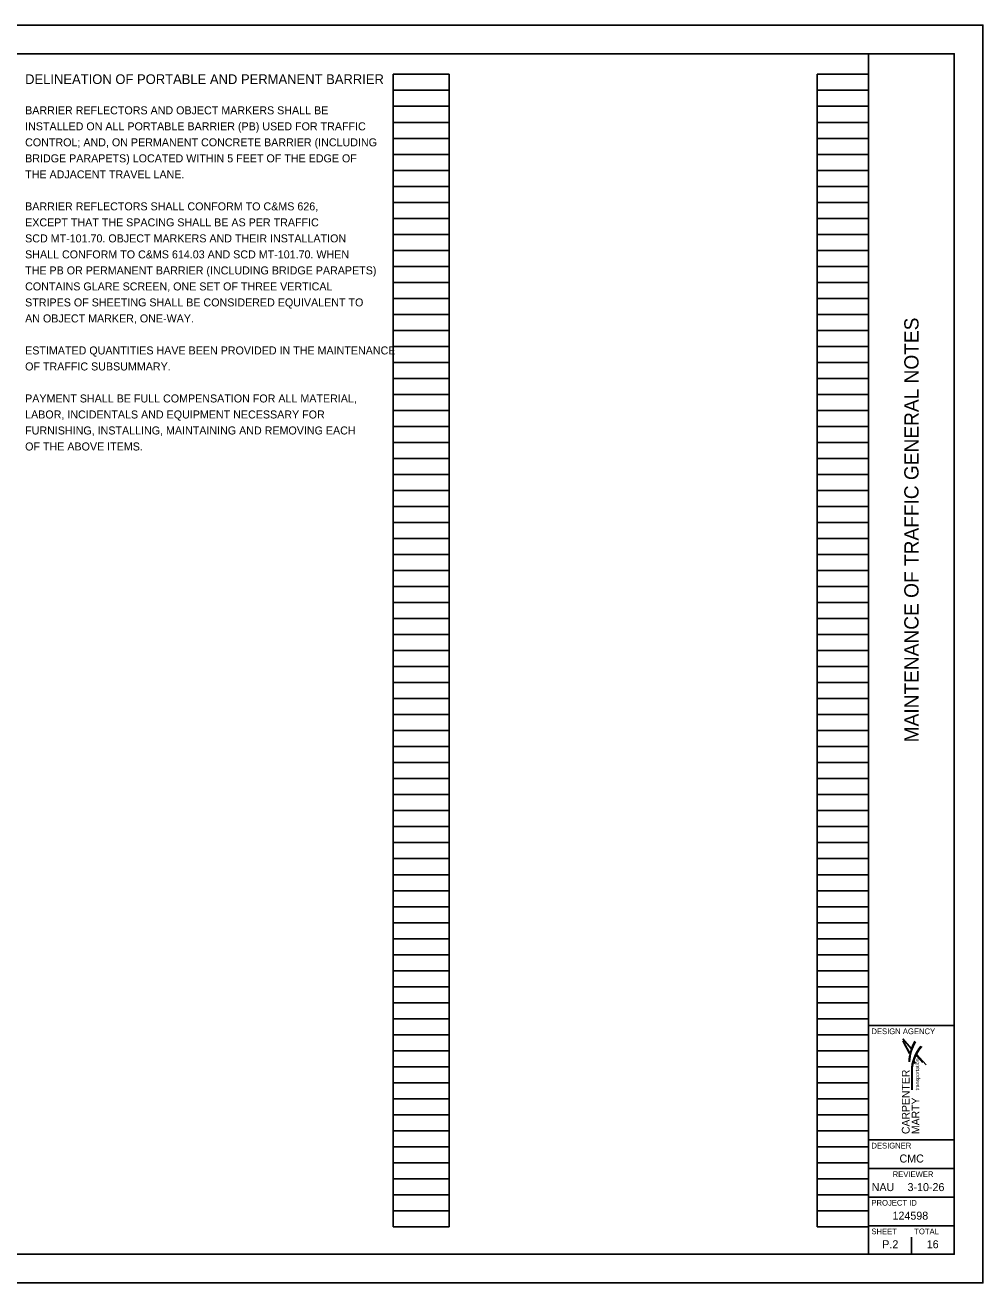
# Model space of a CAD drawing. Extents: x 0 to 34, y 0 to 22.
# Drawn here: x 17.24 to 34, y 0 to 22 of the extents above; entities that cross this region are included whole.
import ezdxf

# ---------------------------------------------------------------- set-up
doc = ezdxf.new("R2010")
doc.units = 0
for name, color, linetype in [('SH_Border', 7, 'Continuous'), ('SH_Cut_Line', 7, 'Continuous'), ('SH_Data', 7, 'Continuous'), ('SH_Text', 7, 'Continuous')]:
    doc.layers.add(name, color=color, linetype=linetype)

msp = doc.modelspace()

# ---------------------------------------------------------------- linework, layer by layer
at = {"layer": 'SH_Border'}
for p, q in [((32, 0.5), (32, 21.5)), ((32, 4.5), (33.5, 4.5)), ((32, 2.5), (33.5, 2.5)), ((32, 2), (33.5, 2)), ((32, 1.5), (33.5, 1.5)), ((32, 1), (33.5, 1))]:
    msp.add_line(p, q, dxfattribs=at)
msp.add_lwpolyline([(1.5, 21.5), (33.5, 21.5), (33.5, 0.5), (1.5, 0.5)], close=True, dxfattribs=at)
at = {"layer": 'SH_Cut_Line'}
msp.add_lwpolyline([(0, 0), (34, 0), (34, 22), (0, 22)], close=True, dxfattribs=at)
at = {"layer": 'SH_Data'}
for p, q in [((23.68, 0.98), (23.68, 21.14)), ((23.68, 21.14), (24.66, 21.14)), ((24.66, 0.98), (24.66, 21.14)), ((31.1, 0.98), (31.1, 21.14)), ((31.1, 21.14), (32, 21.14)), ((32, 0.98), (32, 21.14)), ((23.68, 20.86), (24.66, 20.86)), ((31.1, 20.86), (32, 20.86)), ((23.68, 20.58), (24.66, 20.58)), ((31.1, 20.58), (32, 20.58)), ((23.68, 20.3), (24.66, 20.3)), ((31.1, 20.3), (32, 20.3)), ((23.68, 20.02), (24.66, 20.02)), ((31.1, 20.02), (32, 20.02)), ((23.68, 19.74), (24.66, 19.74)), ((31.1, 19.74), (32, 19.74)), ((23.68, 19.46), (24.66, 19.46)), ((31.1, 19.46), (32, 19.46)), ((23.68, 19.18), (24.66, 19.18)), ((31.1, 19.18), (32, 19.18)), ((23.68, 18.9), (24.66, 18.9)), ((31.1, 18.9), (32, 18.9)), ((23.68, 18.62), (24.66, 18.62)), ((31.1, 18.62), (32, 18.62)), ((23.68, 18.34), (24.66, 18.34)), ((31.1, 18.34), (32, 18.34)), ((23.68, 18.06), (24.66, 18.06)), ((31.1, 18.06), (32, 18.06)), ((23.68, 17.78), (24.66, 17.78)), ((31.1, 17.78), (32, 17.78)), ((23.68, 17.5), (24.66, 17.5)), ((31.1, 17.5), (32, 17.5)), ((23.68, 17.22), (24.66, 17.22)), ((31.1, 17.22), (32, 17.22)), ((23.68, 16.94), (24.66, 16.94)), ((31.1, 16.94), (32, 16.94)), ((23.68, 16.66), (24.66, 16.66)), ((31.1, 16.66), (32, 16.66)), ((23.68, 16.38), (24.66, 16.38)), ((31.1, 16.38), (32, 16.38)), ((23.68, 16.1), (24.66, 16.1)), ((31.1, 16.1), (32, 16.1)), ((23.68, 15.82), (24.66, 15.82)), ((31.1, 15.82), (32, 15.82)), ((23.68, 15.54), (24.66, 15.54)), ((31.1, 15.54), (32, 15.54)), ((23.68, 15.26), (24.66, 15.26)), ((31.1, 15.26), (32, 15.26)), ((23.68, 14.98), (24.66, 14.98)), ((31.1, 14.98), (32, 14.98)), ((23.68, 14.7), (24.66, 14.7)), ((31.1, 14.7), (32, 14.7)), ((23.68, 14.42), (24.66, 14.42)), ((31.1, 14.42), (32, 14.42)), ((23.68, 14.14), (24.66, 14.14)), ((31.1, 14.14), (32, 14.14)), ((23.68, 13.86), (24.66, 13.86)), ((31.1, 13.86), (32, 13.86)), ((23.68, 13.58), (24.66, 13.58)), ((31.1, 13.58), (32, 13.58)), ((23.68, 13.3), (24.66, 13.3)), ((31.1, 13.3), (32, 13.3)), ((23.68, 13.02), (24.66, 13.02)), ((31.1, 13.02), (32, 13.02)), ((23.68, 12.74), (24.66, 12.74)), ((31.1, 12.74), (32, 12.74)), ((23.68, 12.46), (24.66, 12.46)), ((31.1, 12.46), (32, 12.46)), ((23.68, 12.18), (24.66, 12.18)), ((31.1, 12.18), (32, 12.18)), ((23.68, 11.9), (24.66, 11.9)), ((31.1, 11.9), (32, 11.9)), ((23.68, 11.62), (24.66, 11.62)), ((31.1, 11.62), (32, 11.62)), ((23.68, 11.34), (24.66, 11.34)), ((31.1, 11.34), (32, 11.34)), ((23.68, 11.06), (24.66, 11.06)), ((31.1, 11.06), (32, 11.06)), ((23.68, 10.78), (24.66, 10.78)), ((31.1, 10.78), (32, 10.78)), ((23.68, 10.5), (24.66, 10.5)), ((31.1, 10.5), (32, 10.5)), ((23.68, 10.22), (24.66, 10.22)), ((31.1, 10.22), (32, 10.22)), ((23.68, 9.94), (24.66, 9.94)), ((31.1, 9.94), (32, 9.94)), ((23.68, 9.66), (24.66, 9.66)), ((31.1, 9.66), (32, 9.66)), ((23.68, 9.38), (24.66, 9.38)), ((31.1, 9.38), (32, 9.38)), ((23.68, 9.1), (24.66, 9.1)), ((31.1, 9.1), (32, 9.1)), ((23.68, 8.82), (24.66, 8.82)), ((31.1, 8.82), (32, 8.82)), ((23.68, 8.54), (24.66, 8.54)), ((31.1, 8.54), (32, 8.54)), ((23.68, 8.26), (24.66, 8.26)), ((31.1, 8.26), (32, 8.26)), ((23.68, 7.98), (24.66, 7.98)), ((31.1, 7.98), (32, 7.98)), ((23.68, 7.7), (24.66, 7.7)), ((31.1, 7.7), (32, 7.7)), ((23.68, 7.42), (24.66, 7.42)), ((31.1, 7.42), (32, 7.42)), ((23.68, 7.14), (24.66, 7.14)), ((31.1, 7.14), (32, 7.14)), ((23.68, 6.86), (24.66, 6.86)), ((31.1, 6.86), (32, 6.86)), ((23.68, 6.58), (24.66, 6.58)), ((31.1, 6.58), (32, 6.58)), ((23.68, 6.3), (24.66, 6.3)), ((31.1, 6.3), (32, 6.3)), ((23.68, 6.02), (24.66, 6.02)), ((31.1, 6.02), (32, 6.02)), ((23.68, 5.74), (24.66, 5.74)), ((31.1, 5.74), (32, 5.74)), ((23.68, 5.46), (24.66, 5.46)), ((31.1, 5.46), (32, 5.46)), ((23.68, 5.18), (24.66, 5.18)), ((31.1, 5.18), (32, 5.18)), ((23.68, 4.9), (24.66, 4.9)), ((31.1, 4.9), (32, 4.9)), ((23.68, 4.62), (24.66, 4.62)), ((31.1, 4.62), (32, 4.62)), ((23.68, 4.34), (24.66, 4.34)), ((31.1, 4.34), (32, 4.34)), ((23.68, 4.06), (24.66, 4.06)), ((31.1, 4.06), (32, 4.06)), ((23.68, 3.78), (24.66, 3.78)), ((31.1, 3.78), (32, 3.78)), ((23.68, 3.5), (24.66, 3.5)), ((31.1, 3.5), (32, 3.5)), ((32.75, 3.5), (32.75, 3.5)), ((23.68, 3.22), (24.66, 3.22)), ((31.1, 3.22), (32, 3.22)), ((23.68, 2.94), (24.66, 2.94)), ((31.1, 2.94), (32, 2.94)), ((23.68, 2.66), (24.66, 2.66)), ((31.1, 2.66), (32, 2.66)), ((23.68, 2.38), (24.66, 2.38)), ((31.1, 2.38), (32, 2.38)), ((23.68, 2.1), (24.66, 2.1)), ((31.1, 2.1), (32, 2.1)), ((23.68, 1.82), (24.66, 1.82)), ((31.1, 1.82), (32, 1.82)), ((23.68, 1.54), (24.66, 1.54)), ((31.1, 1.54), (32, 1.54)), ((23.68, 1.26), (24.66, 1.26)), ((31.1, 1.26), (32, 1.26)), ((23.68, 0.98), (24.66, 0.98)), ((31.1, 0.98), (32, 0.98)), ((32.375, 0.675), (32.375, 0.675)), ((32.75, 0.5), (32.75, 0.8))]:
    msp.add_line(p, q, dxfattribs=at)
at = {"layer": 'SH_Text'}
for p, q in [((32.721, 4.016), (32.602, 4.232)), ((32.952, 3.853), (32.834, 3.991)), ((32.839, 4.002), (33.006, 3.816)), ((32.811, 3.84), (32.79, 3.88)), ((32.82, 3.834), (32.791, 3.886)), ((32.755, 3.378), (32.755, 3.704)), ((32.762, 3.378), (32.762, 3.704))]:
    msp.add_line(p, q, dxfattribs=at)
for points in [[(32.746, 4.104), (32.601, 4.266)], [(32.601, 4.266), (32.744, 4.098)], [(32.721, 4.016), (32.602, 4.232)], [(32.602, 4.232), (32.719, 4.011)]]:
    msp.add_lwpolyline(points, dxfattribs=at)
for centre, radius, start, end in [((33.432, 3.86), 0.721, 149.5704, 179.5529), ((33.373, 3.862), 0.654, 147.1423, 179.6525), ((33.426, 3.704), 0.671, 139.2898, 180.0106), ((33.433, 3.688), 0.672, 138.5126, 178.6075)]:
    msp.add_arc(centre, radius, start, end, dxfattribs=at)

# ---------------------------------------------------------------- texts
at = {"layer": 'SH_Data'}
msp.add_text('MAINTENANCE OF TRAFFIC GENERAL NOTES', height=0.25, rotation=90, dxfattribs=at).set_placement((32.875, 9.455))
for s, height, p in [('DESIGN AGENCY', 0.1, (32.05, 4.35)), ('DESIGNER', 0.1, (32.05, 2.35)), ('CMC', 0.14, (32.541, 2.105)), ('REVIEWER', 0.1, (32.422, 1.85)), ('NAU', 0.14, (32.055, 1.605)), ('3-10-26', 0.14, (32.682, 1.605)), ('PROJECT ID', 0.1, (32.05, 1.35)), ('124598', 0.14, (32.419, 1.105)), ('SHEET', 0.1, (32.05, 0.85)), ('TOTAL', 0.1, (32.8, 0.85)), ('P.2', 0.14, (32.24, 0.605)), ('16', 0.14, (33.018, 0.605))]:
    msp.add_text(s, height=height, dxfattribs=at).set_placement(p)
at = {"layer": 'SH_Text'}
for s, height, p in [('DELINEATION OF PORTABLE AND PERMANENT BARRIER', 0.17, (17.24, 20.97)), ('BARRIER REFLECTORS AND OBJECT MARKERS SHALL BE', 0.14, (17.24, 20.44)), ('INSTALLED ON ALL PORTABLE BARRIER (PB) USED FOR TRAFFIC', 0.14, (17.24, 20.16)), ('CONTROL; AND, ON PERMANENT CONCRETE BARRIER (INCLUDING', 0.14, (17.24, 19.88)), ('BRIDGE PARAPETS) LOCATED WITHIN 5 FEET OF THE EDGE OF', 0.14, (17.24, 19.6)), ('THE ADJACENT TRAVEL LANE.', 0.14, (17.24, 19.32)), ('BARRIER REFLECTORS SHALL CONFORM TO C&MS 626,', 0.14, (17.24, 18.76)), ('EXCEPT THAT THE SPACING SHALL BE AS PER TRAFFIC', 0.14, (17.24, 18.48)), ('SCD MT-101.70. OBJECT MARKERS AND THEIR INSTALLATION', 0.14, (17.24, 18.2)), ('SHALL CONFORM TO C&MS 614.03 AND SCD MT-101.70. WHEN', 0.14, (17.24, 17.92)), ('THE PB OR PERMANENT BARRIER (INCLUDING BRIDGE PARAPETS)', 0.14, (17.24, 17.64)), ('CONTAINS GLARE SCREEN, ONE SET OF THREE VERTICAL', 0.14, (17.24, 17.36)), ('STRIPES OF SHEETING SHALL BE CONSIDERED EQUIVALENT TO', 0.14, (17.24, 17.08)), ('AN OBJECT MARKER, ONE-WAY.', 0.14, (17.24, 16.8)), ('ESTIMATED QUANTITIES HAVE BEEN PROVIDED IN THE MAINTENANCE ', 0.14, (17.24, 16.24)), ('OF TRAFFIC SUBSUMMARY.', 0.14, (17.24, 15.96)), ('PAYMENT SHALL BE FULL COMPENSATION FOR ALL MATERIAL,', 0.14, (17.24, 15.4)), ('LABOR, INCIDENTALS AND EQUIPMENT NECESSARY FOR', 0.14, (17.24, 15.12)), ('FURNISHING, INSTALLING, MAINTAINING AND REMOVING EACH', 0.14, (17.24, 14.84)), ('OF THE ABOVE ITEMS.', 0.14, (17.24, 14.56))]:
    msp.add_text(s, height=height, dxfattribs=at).set_placement(p)
for s, height, p in [('transportation', 0.06649, (32.885, 3.364)), ('CARPENTER ', 0.1367, (32.719, 2.602)), ('MARTY', 0.1367, (32.891, 2.602))]:
    msp.add_text(s, height=height, rotation=90, dxfattribs=at).set_placement(p)

doc.saveas('drawing.dxf')
